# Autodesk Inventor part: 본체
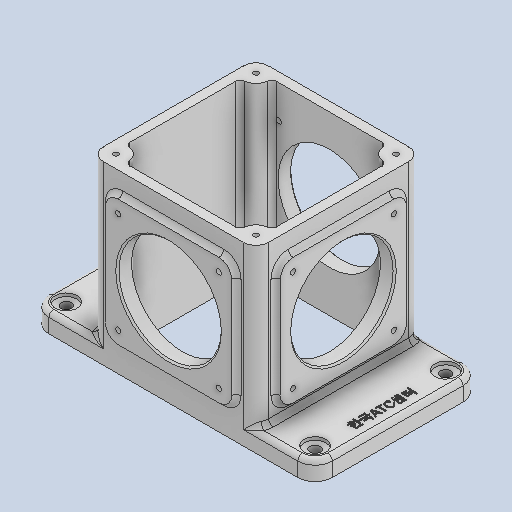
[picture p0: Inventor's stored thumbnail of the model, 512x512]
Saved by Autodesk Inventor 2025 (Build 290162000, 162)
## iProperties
Created: 2024-08
Part Number: 본체
Material: 일반
Document SubType Name: Modeling
Designer: rese9
Density: 1 g/cm^3
Appearance: 기본값
Sending System: Autodesk Inventor 2025
Preprocessor: ST-DEVELOPER v20
Author: jhkim
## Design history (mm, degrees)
feature "솔리드1"
node "솔리드2"
